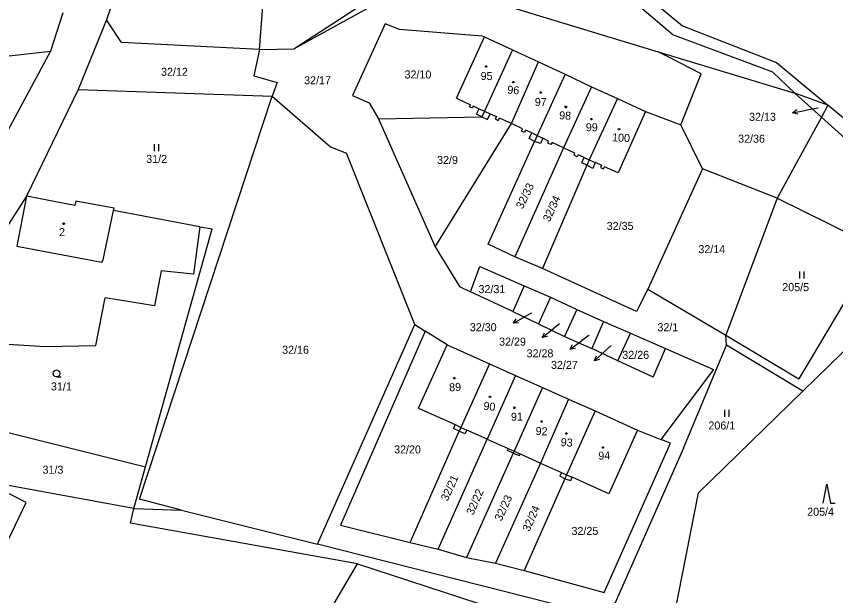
# Model space of a CAD drawing. Extents: x -811039 to -805820, y -1161436 to -1155864.
# Drawn here: x -806560.9 to -806387, y -1158211 to -1158088 of the extents above; entities that cross this region are included whole.
import ezdxf

# ---------------------------------------------------------------- set-up
doc = ezdxf.new("R2010")
doc.units = 0
for name, color, linetype in [('Default', 7, 'Continuous'), ('KN_HRANICE', 7, 'Continuous'), ('KN_KULTURY', 7, 'Continuous'), ('KN_PARCELY', 7, 'Continuous'), ('KN_SLUCKY', 7, 'Continuous')]:
    doc.layers.add(name, color=color, linetype=linetype)

# ---------------------------------------------------------------- blocks, each defined once
blk = doc.blocks.new('304')
at = {"layer": 'Default'}
blk.add_lwpolyline([(0, 0), (-0.38, 0.1), (-0.65, 0.37), (-0.75, 0.74), (-0.65, 1.11), (-0.38, 1.38), (-0.01, 1.48), (0.36, 1.38), (0.63, 1.11), (0.73, 0.73), (0.63, 0.35), (0.36, 0.08), (-0.02, -0.02), (0.98, -0.02)], dxfattribs=at)
blk = doc.blocks.new('306')
at = {"layer": 'Default'}
for p, q in [((-0.5, 1.5), (-0.5, 0)), ((0.5, 0), (0.5, 1.5))]:
    blk.add_line(p, q, dxfattribs=at)
blk = doc.blocks.new('308')
at = {"layer": 'Default'}
blk.add_lwpolyline([(-0.75, 0), (0, 4), (0.75, 0), (1.75, 0)], dxfattribs=at)
blk = doc.blocks.new('10292')
at = {"layer": 'Default'}
blk.add_line((0, 3), (0, 0), dxfattribs=at)
blk.add_lwpolyline([(-0.5, 2), (0, 3), (0.5, 2)], dxfattribs=at)
blk = doc.blocks.new('402')
at = {"layer": 'Default'}
blk.add_lwpolyline([(0.09, 0.15), (0.18, 0), (0.09, -0.15), (-0.09, -0.15), (-0.18, 0), (-0.09, 0.15), (0.09, 0.15)], dxfattribs=at)

msp = doc.modelspace()

# ---------------------------------------------------------------- linework, layer by layer
at = {"layer": 'KN_HRANICE'}
for p, q in [((-806421.5, -1158091.87), (-806450.67, -1158067.18)), ((-806448.04, -1158066.18), (-806419.5, -1158089.94)), ((-806502.01, -1158094.85), (-806478.06, -1158079.22)), ((-806538.91, -1158080.23), (-806541.73, -1158088.69)), ((-806509.31, -1158095.01), (-806508.21, -1158080.94)), ((-806468.91, -1158082), (-806424.62, -1158095.47)), ((-806502.01, -1158094.85), (-806481.45, -1158083.51)), ((-806551.02, -1158087.22), (-806553.63, -1158095.33)), ((-806541.73, -1158088.69), (-806547.81, -1158103.46)), ((-806538.55, -1158093.51), (-806541.73, -1158088.69)), ((-806482.58, -1158089.54), (-806489.52, -1158104.79)), ((-806479.55, -1158090.73), (-806482.58, -1158089.54)), ((-806461.99, -1158092.15), (-806479.55, -1158090.73)), ((-806419.5, -1158089.94), (-806399.53, -1158097.72)), ((-806467.48, -1158105.31), (-806461.55, -1158092.33)), ((-806461.55, -1158092.33), (-806461.99, -1158092.15)), ((-806461.55, -1158092.33), (-806455.58, -1158095.08)), ((-806400.31, -1158099.79), (-806421.5, -1158091.87)), ((-806509.31, -1158095.01), (-806538.55, -1158093.51)), ((-806509.31, -1158095.01), (-806510.48, -1158100.58)), ((-806509.31, -1158095.01), (-806502.01, -1158094.85)), ((-806578.67, -1158098.14), (-806553.63, -1158095.33)), ((-806553.63, -1158095.33), (-806563.21, -1158113.11)), ((-806455.58, -1158095.08), (-806461.52, -1158108.08)), ((-806455.58, -1158095.08), (-806450.03, -1158097.61)), ((-806424.62, -1158095.47), (-806395.6, -1158104.29)), ((-806422.35, -1158096.64), (-806424.62, -1158095.47)), ((-806415.55, -1158100.16), (-806422.35, -1158096.64)), ((-806455.76, -1158110.73), (-806450.03, -1158097.61)), ((-806450.03, -1158097.61), (-806444.41, -1158100.23)), ((-806399.53, -1158097.72), (-806388.61, -1158106.79)), ((-806444.41, -1158100.23), (-806450.31, -1158113.24)), ((-806444.41, -1158100.23), (-806438.81, -1158102.92)), ((-806419.83, -1158110.97), (-806415.55, -1158100.16)), ((-806395.6, -1158104.29), (-806400.31, -1158099.79)), ((-806510.48, -1158100.58), (-806505.56, -1158102.01)), ((-806547.81, -1158103.46), (-806558.78, -1158126.18)), ((-806547.81, -1158103.46), (-806506.58, -1158104.87)), ((-806505.56, -1158102.01), (-806506.58, -1158104.87)), ((-806438.81, -1158102.92), (-806444.72, -1158115.9)), ((-806438.81, -1158102.92), (-806433.28, -1158105.42)), ((-806534.77, -1158190.5), (-806506.58, -1158104.87)), ((-806506.58, -1158104.87), (-806494.21, -1158115.66)), ((-806489.52, -1158104.79), (-806485.99, -1158106.32)), ((-806467.48, -1158105.31), (-806464.52, -1158106.73)), ((-806433.28, -1158105.42), (-806439.27, -1158118.43)), ((-806433.28, -1158105.42), (-806427.32, -1158108.14)), ((-806388.61, -1158106.79), (-806395.6, -1158104.29)), ((-806395.6, -1158104.29), (-806390, -1158109.34)), ((-806485.99, -1158106.32), (-806484.04, -1158109.7)), ((-806464.73, -1158107.17), (-806464.52, -1158106.73)), ((-806464.08, -1158107.46), (-806464.73, -1158107.17)), ((-806463.89, -1158106.97), (-806464.08, -1158107.46)), ((-806463.89, -1158106.97), (-806462.64, -1158107.56)), ((-806388.61, -1158106.79), (-806390, -1158109.34)), ((-806357.33, -1158133.11), (-806388.61, -1158106.79)), ((-806463.18, -1158108.76), (-806462.64, -1158107.56)), ((-806462.08, -1158109.31), (-806463.18, -1158108.76)), ((-806461.52, -1158108.08), (-806462.08, -1158109.31)), ((-806460.85, -1158109.89), (-806460.29, -1158108.64)), ((-806460.29, -1158108.64), (-806459, -1158109.22)), ((-806427.32, -1158108.14), (-806433.16, -1158121.16)), ((-806427.32, -1158108.14), (-806419.83, -1158110.97)), ((-806484.04, -1158109.7), (-806462.08, -1158109.31)), ((-806484.04, -1158109.7), (-806471.98, -1158136.9)), ((-806462.08, -1158109.31), (-806460.85, -1158109.89)), ((-806459, -1158109.22), (-806459.23, -1158109.72)), ((-806459.23, -1158109.72), (-806458.59, -1158110.05)), ((-806458.59, -1158110.05), (-806458.3, -1158109.55)), ((-806455.76, -1158110.73), (-806458.3, -1158109.55)), ((-806390, -1158109.34), (-806399.36, -1158126.56)), ((-806366.79, -1158130.31), (-806390, -1158109.34)), ((-806471.98, -1158136.9), (-806455.76, -1158110.73)), ((-806453.44, -1158111.82), (-806455.76, -1158110.73)), ((-806453.67, -1158112.33), (-806453.44, -1158111.82)), ((-806453.02, -1158112.63), (-806453.67, -1158112.33)), ((-806452.84, -1158112.1), (-806453.02, -1158112.63)), ((-806451.44, -1158112.7), (-806452.84, -1158112.1)), ((-806415.24, -1158120.34), (-806419.83, -1158110.97)), ((-806452, -1158113.92), (-806451.44, -1158112.7)), ((-806450.88, -1158114.5), (-806452, -1158113.92)), ((-806450.31, -1158113.24), (-806450.88, -1158114.5)), ((-806449.11, -1158113.82), (-806449.63, -1158114.95)), ((-806447.92, -1158114.45), (-806449.11, -1158113.82)), ((-806494.21, -1158115.66), (-806490.8, -1158117.03)), ((-806460.71, -1158136.33), (-806450.88, -1158114.5)), ((-806449.63, -1158114.95), (-806450.88, -1158114.5)), ((-806448.07, -1158114.89), (-806447.92, -1158114.45)), ((-806447.43, -1158115.19), (-806448.07, -1158114.89)), ((-806447.14, -1158114.77), (-806447.43, -1158115.19)), ((-806444.72, -1158115.9), (-806447.14, -1158114.77)), ((-806476.33, -1158153.44), (-806490.8, -1158117.03)), ((-806444.72, -1158115.9), (-806455.06, -1158139)), ((-806442.33, -1158117.02), (-806444.72, -1158115.9)), ((-806442.5, -1158117.47), (-806442.33, -1158117.02)), ((-806441.86, -1158117.78), (-806442.5, -1158117.47)), ((-806441.61, -1158117.36), (-806441.86, -1158117.78)), ((-806440.34, -1158117.95), (-806441.61, -1158117.36)), ((-806440.82, -1158119.06), (-806440.34, -1158117.95)), ((-806439.81, -1158119.59), (-806440.82, -1158119.06)), ((-806439.27, -1158118.43), (-806439.81, -1158119.59)), ((-806437.99, -1158119), (-806438.55, -1158120.25)), ((-806436.69, -1158119.58), (-806437.99, -1158119)), ((-806439.81, -1158119.59), (-806449.18, -1158141.51)), ((-806438.55, -1158120.25), (-806439.81, -1158119.59)), ((-806436.69, -1158119.58), (-806436.9, -1158120.08)), ((-806436.9, -1158120.08), (-806436.27, -1158120.37)), ((-806436.27, -1158120.37), (-806436.02, -1158119.88)), ((-806433.16, -1158121.16), (-806436.02, -1158119.88)), ((-806415.24, -1158120.34), (-806426.84, -1158145.87)), ((-806399.36, -1158126.56), (-806415.24, -1158120.34)), ((-806558.78, -1158126.18), (-806568.02, -1158140.53)), ((-806548.47, -1158128.15), (-806558.78, -1158126.18)), ((-806548.28, -1158127.19), (-806548.47, -1158128.15)), ((-806540.17, -1158128.72), (-806548.28, -1158127.19)), ((-806399.36, -1158126.56), (-806410.31, -1158155.64)), ((-806399.36, -1158126.56), (-806378.19, -1158137.05)), ((-806540.27, -1158129.2), (-806540.17, -1158128.72)), ((-806521.93, -1158132.65), (-806540.27, -1158129.2)), ((-806533.49, -1158183.62), (-806519.3, -1158133.09)), ((-806521.93, -1158132.65), (-806523.28, -1158142.72)), ((-806521.93, -1158132.65), (-806519.3, -1158133.09)), ((-806455.06, -1158139), (-806460.71, -1158136.33)), ((-806471.98, -1158136.9), (-806466.85, -1158145.35)), ((-806378.19, -1158137.05), (-806394.81, -1158164.93)), ((-806449.18, -1158141.51), (-806455.06, -1158139)), ((-806464.46, -1158146.47), (-806462.53, -1158141.08)), ((-806462.53, -1158141.08), (-806453.1, -1158145.22)), ((-806429.23, -1158150.61), (-806449.18, -1158141.51)), ((-806366.81, -1158140.98), (-806393.9, -1158167.57)), ((-806530.13, -1158142), (-806531.56, -1158149.43)), ((-806523.28, -1158142.72), (-806530.13, -1158142)), ((-806466.85, -1158145.35), (-806464.46, -1158146.47)), ((-806453.1, -1158145.22), (-806455.53, -1158150.67)), ((-806453.1, -1158145.22), (-806447.53, -1158147.63)), ((-806455.53, -1158150.67), (-806464.46, -1158146.47)), ((-806426.84, -1158145.87), (-806429.23, -1158150.61)), ((-806426.84, -1158145.87), (-806410.31, -1158155.64)), ((-806544.03, -1158157.86), (-806542.02, -1158147.76)), ((-806531.56, -1158149.43), (-806542.02, -1158147.76)), ((-806447.53, -1158147.63), (-806450.04, -1158153.23)), ((-806447.53, -1158147.63), (-806441.92, -1158150.22)), ((-806455.53, -1158150.67), (-806450.04, -1158153.23)), ((-806441.92, -1158150.22), (-806444.5, -1158155.97)), ((-806441.92, -1158150.22), (-806436.27, -1158152.8)), ((-806496.95, -1158200.1), (-806476.33, -1158153.44)), ((-806476.33, -1158153.44), (-806474.1, -1158154.84)), ((-806450.04, -1158153.23), (-806444.5, -1158155.97)), ((-806436.27, -1158152.8), (-806438.76, -1158158.5)), ((-806436.27, -1158152.8), (-806430.51, -1158155.24)), ((-806474.1, -1158154.84), (-806492.06, -1158196.01)), ((-806469.47, -1158157.74), (-806474.1, -1158154.84)), ((-806433.19, -1158161.11), (-806430.51, -1158155.24)), ((-806430.51, -1158155.24), (-806423.11, -1158158.47)), ((-806410.31, -1158155.64), (-806394.81, -1158164.93)), ((-806410.13, -1158157.79), (-806410.31, -1158155.64)), ((-806565.79, -1158157.41), (-806554.8, -1158158.09)), ((-806444.5, -1158155.97), (-806438.76, -1158158.5)), ((-806554.8, -1158158.09), (-806544.03, -1158157.86)), ((-806475.5, -1158171.21), (-806469.47, -1158157.74)), ((-806469.47, -1158157.74), (-806460.48, -1158161.77)), ((-806433.19, -1158161.11), (-806438.76, -1158158.5)), ((-806425.73, -1158164.6), (-806423.11, -1158158.47)), ((-806423.11, -1158158.47), (-806412.93, -1158162.95)), ((-806419.28, -1158179.7), (-806410.13, -1158157.79)), ((-806393.9, -1158167.57), (-806410.13, -1158157.79)), ((-806460.48, -1158161.77), (-806466.52, -1158175.25)), ((-806460.48, -1158161.77), (-806454.91, -1158164.23)), ((-806425.73, -1158164.6), (-806433.19, -1158161.11)), ((-806454.91, -1158164.23), (-806460.94, -1158177.73)), ((-806454.91, -1158164.23), (-806449.23, -1158166.77)), ((-806412.93, -1158162.95), (-806424.07, -1158177.83)), ((-806449.23, -1158166.77), (-806455.23, -1158180.32)), ((-806449.23, -1158166.77), (-806443.65, -1158169.28)), ((-806393.9, -1158167.57), (-806416.11, -1158189.15)), ((-806443.65, -1158169.28), (-806449.63, -1158182.86)), ((-806443.65, -1158169.28), (-806438.03, -1158171.76)), ((-806475.5, -1158171.21), (-806467.75, -1158174.67)), ((-806438.03, -1158171.76), (-806444.1, -1158185.31)), ((-806438.03, -1158171.76), (-806429.02, -1158175.84)), ((-806467.75, -1158174.67), (-806468.08, -1158175.48)), ((-806566.96, -1158175.3), (-806533.49, -1158183.62)), ((-806477.28, -1158199.72), (-806466.9, -1158176.09)), ((-806466.9, -1158176.09), (-806468.08, -1158175.48)), ((-806466.52, -1158175.25), (-806466.9, -1158176.09)), ((-806465.66, -1158176.63), (-806466.9, -1158176.09)), ((-806465.27, -1158175.85), (-806465.66, -1158176.63)), ((-806460.94, -1158177.73), (-806465.27, -1158175.85)), ((-806429.02, -1158175.84), (-806435.09, -1158189.38)), ((-806429.02, -1158175.84), (-806424.07, -1158177.83)), ((-806471.32, -1158201.12), (-806460.94, -1158177.73)), ((-806460.94, -1158177.73), (-806456.52, -1158179.74)), ((-806422.03, -1158178.59), (-806424.07, -1158177.83)), ((-806456.66, -1158180.14), (-806456.52, -1158179.74)), ((-806455.4, -1158180.7), (-806456.66, -1158180.14)), ((-806436.09, -1158210.34), (-806422.03, -1158178.59)), ((-806419.28, -1158179.7), (-806435.17, -1158215.71)), ((-806455.4, -1158180.7), (-806465.35, -1158202.89)), ((-806455.23, -1158180.32), (-806455.4, -1158180.7)), ((-806455.4, -1158180.7), (-806454.12, -1158181.22)), ((-806454.12, -1158181.22), (-806453.96, -1158180.9)), ((-806453.96, -1158180.9), (-806449.63, -1158182.86)), ((-806535.97, -1158192.47), (-806533.49, -1158183.62)), ((-806449.63, -1158182.86), (-806459.21, -1158204.11)), ((-806449.63, -1158182.86), (-806445.17, -1158184.84)), ((-806445.17, -1158184.84), (-806445.49, -1158185.59)), ((-806444.1, -1158185.31), (-806444.49, -1158186.17)), ((-806535.97, -1158192.47), (-806567.76, -1158186.7)), ((-806558.81, -1158191.24), (-806567.76, -1158186.7)), ((-806444.49, -1158186.17), (-806453.12, -1158205.68)), ((-806444.49, -1158186.17), (-806445.49, -1158185.59)), ((-806444.49, -1158186.17), (-806443.19, -1158186.54)), ((-806443.19, -1158186.54), (-806442.88, -1158185.84)), ((-806435.09, -1158189.38), (-806442.88, -1158185.84)), ((-806525.87, -1158192.81), (-806534.77, -1158190.5)), ((-806422.34, -1158220.82), (-806416.11, -1158189.15)), ((-806570.15, -1158214.79), (-806558.81, -1158191.24)), ((-806536.67, -1158195.62), (-806535.97, -1158192.47)), ((-806535.97, -1158192.47), (-806525.87, -1158192.81)), ((-806525.87, -1158192.81), (-806496.95, -1158200.1)), ((-806488.49, -1158204.22), (-806536.67, -1158195.62)), ((-806492.06, -1158196.01), (-806477.28, -1158199.72)), ((-806435.17, -1158215.71), (-806496.95, -1158200.1)), ((-806477.28, -1158199.72), (-806471.32, -1158201.12)), ((-806471.32, -1158201.12), (-806465.35, -1158202.89)), ((-806509.26, -1158239.64), (-806488.49, -1158204.22)), ((-806488.49, -1158204.22), (-806428.22, -1158223.9)), ((-806465.35, -1158202.89), (-806459.21, -1158204.11)), ((-806459.21, -1158204.11), (-806453.12, -1158205.68)), ((-806453.12, -1158205.68), (-806436.09, -1158210.34))]:
    msp.add_line(p, q, dxfattribs=at)
at = {"layer": 'KN_PARCELY'}
for p, q in [((-806390.66, -1158107.47), (-806393.15, -1158107.91)), ((-806451.56, -1158150.98), (-806452.77, -1158151.66)), ((-806445.59, -1158153.24), (-806446.92, -1158154.31)), ((-806439.4, -1158155.77), (-806440.92, -1158156.89)), ((-806434.6, -1158157.86), (-806435.95, -1158159.1))]:
    msp.add_line(p, q, dxfattribs=at)
at = {"layer": 'KN_SLUCKY'}
for p, q in [((-806462.64, -1158107.56), (-806461.52, -1158108.08)), ((-806461.52, -1158108.08), (-806460.29, -1158108.64)), ((-806451.44, -1158112.7), (-806450.31, -1158113.24)), ((-806450.31, -1158113.24), (-806449.11, -1158113.82)), ((-806440.34, -1158117.95), (-806439.27, -1158118.43)), ((-806439.27, -1158118.43), (-806437.99, -1158119)), ((-806558.78, -1158126.18), (-806560.77, -1158136.74)), ((-806542.45, -1158139.7), (-806540.27, -1158129.2)), ((-806560.77, -1158136.74), (-806542.74, -1158140.14)), ((-806542.74, -1158140.14), (-806542.45, -1158139.7)), ((-806467.75, -1158174.67), (-806466.52, -1158175.25)), ((-806466.52, -1158175.25), (-806465.27, -1158175.85)), ((-806456.52, -1158179.74), (-806455.23, -1158180.32)), ((-806455.23, -1158180.32), (-806453.96, -1158180.9)), ((-806445.17, -1158184.84), (-806444.1, -1158185.31)), ((-806444.1, -1158185.31), (-806442.88, -1158185.84))]:
    msp.add_line(p, q, dxfattribs=at)

# ---------------------------------------------------------------- block references
at = {"layer": 'KN_KULTURY'}
for name, p in [('402', (-806461.16, -1158098.61)), ('402', (-806455.41, -1158101.92)), ('402', (-806449.57, -1158104.15)), ('402', (-806444.25, -1158107.21)), ('402', (-806438.81, -1158109.8)), ('402', (-806432.97, -1158111.91)), ('306', (-806531.13, -1158116.6)), ('402', (-806550.86, -1158131.99)), ('306', (-806394.17, -1158143.62)), ('304', (-806552.37, -1158164.53)), ('402', (-806467.91, -1158164.79)), ('402', (-806460.36, -1158168.77)), ('402', (-806455.16, -1158171.07)), ('306', (-806410.09, -1158173)), ('402', (-806449.4, -1158174.03)), ('402', (-806444.16, -1158176.57)), ('402', (-806436.39, -1158179.54)), ('308', (-806388.84, -1158191.33))]:
    msp.add_blockref(name, p, dxfattribs=at)
at = {"layer": 'KN_PARCELY'}
for p, rotation in [((-806393.15, -1158107.91), 100.09572699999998), ((-806452.77, -1158151.66), 119.347109), ((-806446.92, -1158154.31), 128.9728), ((-806440.92, -1158156.89), 126.509081), ((-806435.95, -1158159.1), 132.754321)]:
    msp.add_blockref('10292', p, dxfattribs=dict(at, rotation=rotation))

# ---------------------------------------------------------------- texts
for s, height, p in [('32/12', 1.7, (-806530.19, -1158100.58)), ('32/10', 1.7, (-806478.49, -1158101.14)), ('32/17', 1.7, (-806499.81, -1158102.38)), ('32/13', 1.7, (-806405.35, -1158110.14)), ('32/13', 0.1, (-806390.9, -1158107.47)), ('32/36', 1.7, (-806407.67, -1158114.79)), ('31/2', 1.7, (-806533.33, -1158119.08)), ('32/9', 1.7, (-806471.58, -1158119.3)), ('32/35', 1.7, (-806435.57, -1158133.31)), ('2', 1.7, (-806551.83, -1158134.63)), ('32/14', 1.7, (-806416.11, -1158138.25)), ('32/31', 1.7, (-806462.79, -1158146.74)), ('205/5', 1.7, (-806398.3, -1158146.32)), ('32/30', 0.1, (-806451.55, -1158150.98)), ('32/30', 1.7, (-806464.63, -1158154.83)), ('32/29', 0.1, (-806445.83, -1158153.24)), ('32/1', 1.7, (-806424.8, -1158154.83)), ('32/28', 0.1, (-806439.39, -1158155.77)), ('32/29', 1.7, (-806458.42, -1158157.9)), ('32/16', 1.7, (-806504.48, -1158159.62)), ('32/28', 1.7, (-806452.58, -1158160.38)), ('32/27', 0.1, (-806434.84, -1158157.86)), ('32/26', 1.7, (-806432.26, -1158160.7)), ('32/27', 1.7, (-806447.4, -1158162.84)), ('31/1', 1.7, (-806553.55, -1158167.41)), ('206/1', 1.7, (-806413.98, -1158175.7)), ('32/20', 1.7, (-806480.71, -1158180.79)), ('31/3', 1.7, (-806555.34, -1158185.1)), ('205/4', 1.7, (-806393.01, -1158194.03)), ('32/25', 1.7, (-806443.04, -1158198.1))]:
    msp.add_text(s, height=height, dxfattribs=at).set_placement(p)
for s, rotation, p in [('95', 359.875, (-806462.34, -1158101.46)), ('96', 355.578, (-806456.72, -1158104.35)), ('97', 359.302, (-806450.85, -1158106.99)), ('98', 356.609, (-806445.71, -1158109.78)), ('99', 0.229, (-806440, -1158112.37)), ('100', 357.296, (-806434.46, -1158114.49)), ('32/33', 64.057, (-806453.42, -1158129.01)), ('32/34', 65.546, (-806447.68, -1158131.72)), ('89', 2.807, (-806468.98, -1158167.61)), ('90', 353.973, (-806461.81, -1158171.51)), ('91', 0.974, (-806455.88, -1158173.85)), ('92', 357.927, (-806450.69, -1158176.87)), ('93', 356.38, (-806445.38, -1158179.22)), ('94', 2.464, (-806437.31, -1158182.13)), ('32/21', 65.546, (-806469.34, -1158191.05)), ('32/22', 66.406, (-806463.91, -1158194.02)), ('32/23', 65.718, (-806457.92, -1158195.31)), ('32/24', 66.177, (-806452, -1158197.54))]:
    msp.add_text(s, height=1.7, rotation=rotation, dxfattribs=at).set_placement(p)

doc.saveas('drawing.dxf')
